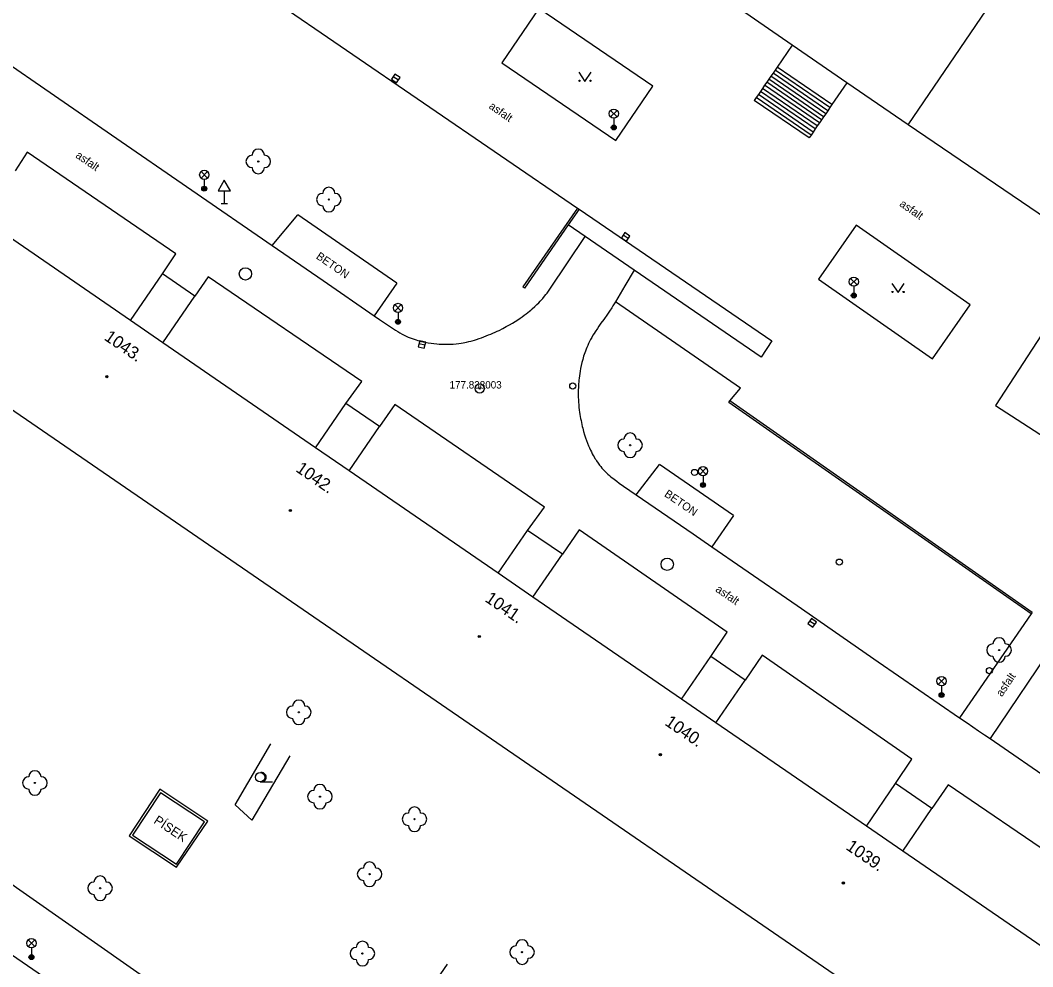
# Model space of a CAD drawing. Extents: x -539515 to -538098, y -1182060 to -1180157.
# Drawn here: x -538629 to -538546.7, y -1181340.3 to -1181263.4 of the extents above; entities that cross this region are included whole.
import ezdxf

# ---------------------------------------------------------------- set-up
doc = ezdxf.new("R2010")
doc.units = 0
for name, color, linetype in [('Vrstva 10', 7, 'Continuous'), ('Vrstva 11', 7, 'Continuous'), ('Vrstva 21', 7, 'Continuous'), ('Vrstva 22', 7, 'Continuous'), ('Vrstva 23', 7, 'Continuous'), ('Vrstva 27', 7, 'Continuous'), ('Vrstva 28', 7, 'Continuous'), ('Vrstva 33', 7, 'Continuous'), ('Vrstva 34', 7, 'Continuous'), ('Vrstva 36', 7, 'Continuous'), ('Vrstva 39', 7, 'Continuous'), ('Vrstva 40', 7, 'Continuous'), ('Vrstva 41', 7, 'Continuous'), ('Vrstva 47', 7, 'Continuous'), ('Vrstva 5', 7, 'Continuous'), ('Vrstva 7', 7, 'Continuous')]:
    doc.layers.add(name, color=color, linetype=linetype)

msp = doc.modelspace()

# ---------------------------------------------------------------- linework, layer by layer
at = {"layer": 'Vrstva 10'}
for p, q in [((-538634.64, -1181263.75), (-538621.575, -1181272.74)), ((-538621.575, -1181272.74), (-538608.51, -1181281.73)), ((-538608.51, -1181281.73), (-538604.369, -1181284.584)), ((-538584.53, -1181283.145), (-538583.1, -1181281.01)), ((-538604.369, -1181284.584), (-538600.23, -1181287.44)), ((-538572.79, -1181306.2), (-538570.276, -1181307.935)), ((-538570.276, -1181307.935), (-538565.881, -1181310.976)), ((-538565.881, -1181310.976), (-538559.29, -1181315.539)), ((-538551.127, -1181321.151), (-538550.658, -1181321.47)), ((-538550.658, -1181321.47), (-538550.19, -1181321.79)), ((-538550.19, -1181321.79), (-538544.771, -1181325.525)), ((-538617.649, -1181325.904), (-538620.15, -1181329.69)), ((-538617.592, -1181326.181), (-538619.873, -1181329.633)), ((-538613.75, -1181328.48), (-538617.649, -1181325.904)), ((-538614.027, -1181328.537), (-538617.592, -1181326.181)), ((-538616.308, -1181331.989), (-538614.027, -1181328.537)), ((-538616.29, -1181332.24), (-538613.75, -1181328.48)), ((-538620.15, -1181329.69), (-538616.29, -1181332.24)), ((-538619.873, -1181329.633), (-538616.308, -1181331.989))]:
    msp.add_line(p, q, dxfattribs=at)
for points in [[(-538590.937, -1181289), (-538590.757, -1181288.925), (-538590.582, -1181288.85), (-538590.413, -1181288.775), (-538590.25, -1181288.699), (-538590.093, -1181288.625), (-538589.789, -1181288.474), (-538589.507, -1181288.326), (-538589.246, -1181288.181), (-538589.004, -1181288.04), (-538588.779, -1181287.903), (-538588.572, -1181287.771), (-538588.38, -1181287.642), (-538588.203, -1181287.519), (-538588.039, -1181287.401), (-538587.888, -1181287.287), (-538587.748, -1181287.178), (-538587.619, -1181287.074), (-538587.5, -1181286.975), (-538587.39, -1181286.88), (-538587.187, -1181286.699), (-538587.015, -1181286.536), (-538586.869, -1181286.39), (-538586.744, -1181286.26), (-538586.637, -1181286.144), (-538586.545, -1181286.041), (-538586.389, -1181285.857), (-538586.277, -1181285.717), (-538586.194, -1181285.609), (-538586.075, -1181285.446), (-538585.96, -1181285.28), (-538584.53, -1181283.145)], [(-538579.12, -1181283.73), (-538579.875, -1181285.02), (-538580.63, -1181286.31), (-538580.735, -1181286.485), (-538580.837, -1181286.648), (-538580.934, -1181286.798), (-538581.121, -1181287.076), (-538581.289, -1181287.317), (-538581.587, -1181287.736), (-538581.811, -1181288.052), (-538581.978, -1181288.291), (-538582.102, -1181288.472), (-538582.284, -1181288.748), (-538582.373, -1181288.888), (-538582.46, -1181289.03), (-538582.559, -1181289.2), (-538582.651, -1181289.368), (-538582.736, -1181289.532), (-538582.814, -1181289.694), (-538582.887, -1181289.852), (-538582.953, -1181290.007), (-538583.015, -1181290.159), (-538583.071, -1181290.307), (-538583.124, -1181290.452), (-538583.172, -1181290.593), (-538583.216, -1181290.731), (-538583.257, -1181290.865), (-538583.294, -1181290.995), (-538583.361, -1181291.25), (-538583.417, -1181291.49), (-538583.465, -1181291.717), (-538583.504, -1181291.93), (-538583.536, -1181292.131), (-538583.563, -1181292.32), (-538583.585, -1181292.497)], [(-538600.23, -1181287.44), (-538599.797, -1181287.737), (-538599.145, -1181288.18), (-538598.49, -1181288.62), (-538598.316, -1181288.732), (-538598.143, -1181288.835), (-538597.971, -1181288.929), (-538597.801, -1181289.016), (-538597.633, -1181289.095), (-538597.468, -1181289.167), (-538597.306, -1181289.233), (-538597.146, -1181289.293), (-538596.99, -1181289.348), (-538596.837, -1181289.398), (-538596.687, -1181289.443), (-538596.54, -1181289.483), (-538596.398, -1181289.52), (-538596.258, -1181289.553), (-538596.123, -1181289.583), (-538595.991, -1181289.609), (-538595.862, -1181289.633), (-538595.612, -1181289.673), (-538595.376, -1181289.703), (-538595.154, -1181289.726), (-538594.945, -1181289.741), (-538594.749, -1181289.751), (-538594.566, -1181289.757), (-538594.394, -1181289.758), (-538594.233, -1181289.756), (-538594.083, -1181289.752), (-538593.942, -1181289.745), (-538593.811, -1181289.737), (-538593.566, -1181289.716), (-538593.353, -1181289.692), (-538593.168, -1181289.666), (-538593.008, -1181289.64), (-538592.869, -1181289.615), (-538592.748, -1181289.59), (-538592.538, -1181289.544), (-538592.383, -1181289.505), (-538592.268, -1181289.474), (-538592.098, -1181289.424), (-538591.93, -1181289.37), (-538591.719, -1181289.298), (-538591.515, -1181289.224), (-538591.316, -1181289.15), (-538591.124, -1181289.076), (-538590.937, -1181289)], [(-538583.585, -1181292.497), (-538583.603, -1181292.663), (-538583.617, -1181292.818), (-538583.629, -1181292.964), (-538583.645, -1181293.237), (-538583.653, -1181293.475), (-538583.656, -1181293.683), (-538583.655, -1181293.863), (-538583.652, -1181294.021), (-538583.641, -1181294.295), (-538583.629, -1181294.499), (-538583.617, -1181294.651), (-538583.596, -1181294.877), (-538583.57, -1181295.1), (-538583.546, -1181295.28), (-538583.52, -1181295.457), (-538583.492, -1181295.629), (-538583.462, -1181295.797), (-538583.431, -1181295.96), (-538583.399, -1181296.119), (-538583.365, -1181296.273), (-538583.331, -1181296.423), (-538583.295, -1181296.568), (-538583.22, -1181296.849), (-538583.143, -1181297.111), (-538583.064, -1181297.356), (-538582.984, -1181297.585), (-538582.904, -1181297.797), (-538582.824, -1181297.994), (-538582.745, -1181298.176), (-538582.667, -1181298.346), (-538582.59, -1181298.503), (-538582.515, -1181298.648), (-538582.442, -1181298.782), (-538582.371, -1181298.907), (-538582.302, -1181299.022), (-538582.236, -1181299.129), (-538582.172, -1181299.227), (-538582.047, -1181299.408), (-538581.933, -1181299.563), (-538581.83, -1181299.695), (-538581.736, -1181299.808), (-538581.652, -1181299.905), (-538581.577, -1181299.988), (-538581.441, -1181300.129), (-538581.335, -1181300.231), (-538581.254, -1181300.306), (-538581.129, -1181300.415), (-538581, -1181300.52), (-538580.745, -1181300.717), (-538580.521, -1181300.885), (-538580.325, -1181301.028)], [(-538580.325, -1181301.028), (-538579.981, -1181301.273)], [(-538579.981, -1181301.273), (-538579.462, -1181301.633), (-538578.94, -1181301.99), (-538575.863, -1181304.093), (-538574.326, -1181305.145), (-538572.79, -1181306.2)], [(-538559.29, -1181315.539), (-538555.992, -1181317.818), (-538554.342, -1181318.955), (-538552.69, -1181320.09), (-538552.066, -1181320.516), (-538551.127, -1181321.151)], [(-538631.15, -1181338.36), (-538630.571, -1181338.752), (-538629.7, -1181339.334), (-538629.264, -1181339.626), (-538628.83, -1181339.92), (-538624.923, -1181342.589)]]:
    msp.add_lwpolyline(points, dxfattribs=at)
at = {"layer": 'Vrstva 11'}
for p, q in [((-538621.123, -1181253.107), (-538583.713, -1181278.704)), ((-538586.85, -1181262.484), (-538589.86, -1181266.91)), ((-538577.59, -1181268.78), (-538586.85, -1181262.484)), ((-538589.86, -1181266.91), (-538580.6, -1181273.206)), ((-538563.384, -1181270.785), (-538567.832, -1181267.733)), ((-538563.214, -1181270.538), (-538567.662, -1181267.486)), ((-538563.044, -1181270.29), (-538567.492, -1181267.238)), ((-538563.893, -1181271.527), (-538568.341, -1181268.475)), ((-538563.723, -1181271.28), (-538568.171, -1181268.228)), ((-538563.554, -1181271.033), (-538568.002, -1181267.981)), ((-538580.6, -1181273.206), (-538577.59, -1181268.78)), ((-538564.402, -1181272.269), (-538568.85, -1181269.217)), ((-538564.233, -1181272.022), (-538568.681, -1181268.97)), ((-538564.063, -1181271.775), (-538568.511, -1181268.723)), ((-538564.89, -1181272.98), (-538569.36, -1181269.96)), ((-538564.742, -1181272.764), (-538569.19, -1181269.712)), ((-538564.572, -1181272.517), (-538569.02, -1181269.465)), ((-538628.43, -1181274.15), (-538629.4, -1181275.68)), ((-538616.34, -1181282.4), (-538628.43, -1181274.15)), ((-538608.51, -1181281.73), (-538606.44, -1181279.25)), ((-538598.404, -1181284.792), (-538606.44, -1181279.25)), ((-538583.59, -1181278.79), (-538567.93, -1181289.48)), ((-538583.1, -1181281.01), (-538584.476, -1181280.067)), ((-538561.09, -1181280.09), (-538564.15, -1181284.46)), ((-538551.82, -1181286.56), (-538561.09, -1181280.09)), ((-538579.12, -1181283.73), (-538583.1, -1181281.01)), ((-538617.43, -1181284.04), (-538616.34, -1181282.4)), ((-538568.8, -1181290.8), (-538579.12, -1181283.73)), ((-538613.73, -1181284.28), (-538614.804, -1181285.844)), ((-538601.25, -1181292.77), (-538613.73, -1181284.28)), ((-538598.404, -1181284.792), (-538600.23, -1181287.44)), ((-538564.15, -1181284.46), (-538554.873, -1181290.935)), ((-538570.48, -1181293.31), (-538580.63, -1181286.31)), ((-538554.873, -1181290.935), (-538551.82, -1181286.56)), ((-538544.914, -1181287.276), (-538549.76, -1181294.73)), ((-538567.93, -1181289.48), (-538568.8, -1181290.8)), ((-538602.53, -1181294.57), (-538601.25, -1181292.77)), ((-538571.34, -1181294.35), (-538570.48, -1181293.31)), ((-538598.56, -1181294.65), (-538599.795, -1181296.448)), ((-538586.4, -1181303), (-538598.56, -1181294.65)), ((-538549.76, -1181294.73), (-538544.386, -1181298.224)), ((-538578.94, -1181301.99), (-538577.06, -1181299.52)), ((-538571.044, -1181303.666), (-538577.06, -1181299.52)), ((-538587.77, -1181304.87), (-538586.4, -1181303)), ((-538571.044, -1181303.666), (-538572.79, -1181306.2)), ((-538583.59, -1181304.83), (-538584.948, -1181306.808)), ((-538571.57, -1181313.13), (-538583.59, -1181304.83)), ((-538540.93, -1181307.99), (-538550.19, -1181321.79)), ((-538546.866, -1181311.663), (-538552.69, -1181320.09)), ((-538572.88, -1181315.11), (-538571.57, -1181313.13)), ((-538568.71, -1181315.02), (-538570.089, -1181317.027)), ((-538556.55, -1181323.45), (-538568.71, -1181315.02)), ((-538557.88, -1181325.44), (-538556.55, -1181323.45)), ((-538553.6, -1181325.54), (-538554.926, -1181327.47)), ((-538541.75, -1181333.61), (-538553.6, -1181325.54)), ((-538632.69, -1181331.5), (-538606.03, -1181350.16))]:
    msp.add_line(p, q, dxfattribs=at)
for points in [[(-538566.272, -1181265.459), (-538571.27, -1181262.03)], [(-538566.272, -1181265.459), (-538567.492, -1181267.238), (-538567.662, -1181267.486), (-538567.832, -1181267.733), (-538568.002, -1181267.981), (-538568.171, -1181268.228), (-538568.341, -1181268.475), (-538568.511, -1181268.723), (-538568.681, -1181268.97), (-538568.85, -1181269.217), (-538569.02, -1181269.465), (-538569.19, -1181269.712), (-538569.36, -1181269.96)], [(-538561.824, -1181268.511), (-538566.272, -1181265.459)], [(-538561.824, -1181268.511), (-538563.044, -1181270.29), (-538563.214, -1181270.538), (-538563.384, -1181270.785), (-538563.554, -1181271.033), (-538563.723, -1181271.28), (-538563.893, -1181271.527), (-538564.063, -1181271.775), (-538564.233, -1181272.022), (-538564.402, -1181272.269), (-538564.572, -1181272.517), (-538564.742, -1181272.764), (-538564.89, -1181272.98)], [(-538556.84, -1181271.93), (-538561.824, -1181268.511)]]:
    msp.add_lwpolyline(points, dxfattribs=at)
at = {"layer": 'Vrstva 21'}
for p, q in [((-538611.54, -1181327.16), (-538608.63, -1181322.21)), ((-538607.09, -1181323.19), (-538610.17, -1181328.4)), ((-538610.17, -1181328.4), (-538611.54, -1181327.16))]:
    msp.add_line(p, q, dxfattribs=at)
for radius in [0.375, 0.05]:
    msp.add_circle((-538591.66, -1181293.35), radius, dxfattribs=at)
at = {"layer": 'Vrstva 22'}
for centre in [(-538609.65, -1181274.91), (-538603.92, -1181278), (-538579.44, -1181297.96), (-538549.46, -1181314.59), (-538606.36, -1181319.65), (-538627.8, -1181325.39), (-538604.64, -1181326.5), (-538596.96, -1181328.33), (-538600.61, -1181332.8), (-538622.5, -1181333.94), (-538601.19, -1181339.24), (-538588.22, -1181339.13)]:
    msp.add_circle(centre, 0.05, dxfattribs=at)
for centre, start, end in [((-538609.65, -1181274.41), 0, 180), ((-538610.15, -1181274.91), 90, 270), ((-538609.15, -1181274.91), 270, 90), ((-538609.65, -1181275.41), 180, 0), ((-538604.42, -1181278), 90, 270), ((-538603.92, -1181277.5), 0, 180), ((-538603.42, -1181278), 270, 90), ((-538603.92, -1181278.5), 180, 0), ((-538579.44, -1181297.46), 0, 180), ((-538579.94, -1181297.96), 90, 270), ((-538578.94, -1181297.96), 270, 90), ((-538579.44, -1181298.46), 180, 0), ((-538549.46, -1181314.09), 0, 180), ((-538549.96, -1181314.59), 90, 270), ((-538548.96, -1181314.59), 270, 90), ((-538549.46, -1181315.09), 180, 0), ((-538606.36, -1181319.15), 0, 180), ((-538606.86, -1181319.65), 90, 270), ((-538605.86, -1181319.65), 270, 90), ((-538606.36, -1181320.15), 180, 0), ((-538627.8, -1181324.89), 0, 180), ((-538628.3, -1181325.39), 90, 270), ((-538627.3, -1181325.39), 270, 90), ((-538627.8, -1181325.89), 180, 0), ((-538605.14, -1181326.5), 90, 270), ((-538604.64, -1181326), 0, 180), ((-538604.14, -1181326.5), 270, 90), ((-538604.64, -1181327), 180, 0), ((-538597.46, -1181328.33), 90, 270), ((-538596.96, -1181327.83), 0, 180), ((-538596.46, -1181328.33), 270, 90), ((-538596.96, -1181328.83), 180, 0), ((-538600.61, -1181332.3), 0, 180), ((-538601.11, -1181332.8), 90, 270), ((-538600.11, -1181332.8), 270, 90), ((-538623, -1181333.94), 90, 270), ((-538622.5, -1181333.44), 0, 180), ((-538622, -1181333.94), 270, 90), ((-538600.61, -1181333.3), 180, 0), ((-538622.5, -1181334.44), 180, 0), ((-538601.19, -1181338.74), 0, 180), ((-538588.22, -1181338.63), 0, 180), ((-538601.69, -1181339.24), 90, 270), ((-538600.69, -1181339.24), 270, 90), ((-538588.72, -1181339.13), 90, 270), ((-538587.72, -1181339.13), 270, 90), ((-538601.19, -1181339.74), 180, 0), ((-538588.22, -1181339.63), 180, 0)]:
    msp.add_arc(centre, 0.5, start, end, dxfattribs=at)
at = {"layer": 'Vrstva 27'}
for p, q in [((-538598.273, -1181268.305), (-538598.685, -1181268.023)), ((-538579.602, -1181281.177), (-538580.014, -1181280.895)), ((-538596.106, -1181289.826), (-538596.594, -1181289.714)), ((-538564.444, -1181312.522), (-538564.856, -1181312.238))]:
    msp.add_line(p, q, dxfattribs=at)
for points in [[(-538598.132, -1181268.099), (-538598.544, -1181267.817), (-538598.826, -1181268.229), (-538598.414, -1181268.511)], [(-538579.461, -1181280.97), (-538579.874, -1181280.689), (-538580.155, -1181281.102), (-538579.742, -1181281.383)], [(-538596.05, -1181289.583), (-538596.537, -1181289.47), (-538596.65, -1181289.957), (-538596.163, -1181290.07)], [(-538564.302, -1181312.317), (-538564.713, -1181312.032), (-538564.998, -1181312.443), (-538564.587, -1181312.728)]]:
    msp.add_lwpolyline(points, close=True, dxfattribs=at)
for centre in [(-538610.7, -1181284.04), (-538576.43, -1181307.63)]:
    msp.add_circle(centre, 0.5, dxfattribs=at)
at = {"layer": 'Vrstva 28'}
for centre in [(-538584.1, -1181293.14), (-538574.21, -1181300.17), (-538562.45, -1181307.45), (-538550.25, -1181316.27)]:
    msp.add_circle(centre, 0.25, dxfattribs=at)
at = {"layer": 'Vrstva 33'}
for p, q in [((-538581.035, -1181271.29), (-538580.505, -1181270.76)), ((-538581.035, -1181270.76), (-538580.505, -1181271.29)), ((-538580.77, -1181271.4), (-538580.77, -1181272.15)), ((-538614.305, -1181276.26), (-538613.775, -1181275.73)), ((-538614.305, -1181275.73), (-538613.775, -1181276.26)), ((-538614.04, -1181276.37), (-538614.04, -1181277.12)), ((-538561.535, -1181284.94), (-538561.005, -1181284.41)), ((-538561.535, -1181284.41), (-538561.005, -1181284.94)), ((-538561.27, -1181285.05), (-538561.27, -1181285.8)), ((-538598.565, -1181287.07), (-538598.035, -1181286.54)), ((-538598.565, -1181286.54), (-538598.035, -1181287.07)), ((-538598.3, -1181287.18), (-538598.3, -1181287.93)), ((-538573.785, -1181300.33), (-538573.255, -1181299.8)), ((-538573.785, -1181299.8), (-538573.255, -1181300.33)), ((-538573.52, -1181300.44), (-538573.52, -1181301.19)), ((-538554.405, -1181317.38), (-538553.875, -1181316.85)), ((-538554.405, -1181316.85), (-538553.875, -1181317.38)), ((-538554.14, -1181317.49), (-538554.14, -1181318.24)), ((-538628.345, -1181338.67), (-538627.815, -1181338.14)), ((-538628.345, -1181338.14), (-538627.815, -1181338.67)), ((-538628.08, -1181338.78), (-538628.08, -1181339.53))]:
    msp.add_line(p, q, dxfattribs=at)
for centre, radius in [((-538580.77, -1181271.025), 0.375), ((-538580.77, -1181272.15), 0.2), ((-538580.77, -1181272.15), 0.145), ((-538580.77, -1181272.15), 0.0876), ((-538614.04, -1181275.995), 0.375), ((-538614.04, -1181277.12), 0.2), ((-538614.04, -1181277.12), 0.145), ((-538614.04, -1181277.12), 0.0876), ((-538561.27, -1181284.675), 0.375), ((-538561.27, -1181285.8), 0.2), ((-538561.27, -1181285.8), 0.145), ((-538561.27, -1181285.8), 0.0876), ((-538598.3, -1181286.805), 0.375), ((-538598.3, -1181287.93), 0.2), ((-538598.3, -1181287.93), 0.145), ((-538598.3, -1181287.93), 0.0876), ((-538573.52, -1181300.065), 0.375), ((-538573.52, -1181301.19), 0.2), ((-538573.52, -1181301.19), 0.145), ((-538573.52, -1181301.19), 0.0876), ((-538554.14, -1181317.115), 0.375), ((-538554.14, -1181318.24), 0.2), ((-538554.14, -1181318.24), 0.145), ((-538554.14, -1181318.24), 0.0876), ((-538628.08, -1181338.405), 0.375), ((-538628.08, -1181339.53), 0.2), ((-538628.08, -1181339.53), 0.145), ((-538628.08, -1181339.53), 0.0876)]:
    msp.add_circle(centre, radius, dxfattribs=at)
at = {"layer": 'Vrstva 34'}
for p, q in [((-538612.414, -1181277.297), (-538612.414, -1181278.315)), ((-538612.664, -1181278.315), (-538612.164, -1181278.315))]:
    msp.add_line(p, q, dxfattribs=at)
msp.add_lwpolyline([(-538612.914, -1181277.297), (-538611.914, -1181277.297), (-538612.414, -1181276.431)], close=True, dxfattribs=at)
at = {"layer": 'Vrstva 36'}
msp.add_line((-538609.504, -1181325.296), (-538608.504, -1181325.296), dxfattribs=at)
for points in [[(-538583.608, -1181267.653), (-538583.108, -1181268.403), (-538582.608, -1181267.653)], [(-538558.174, -1181284.808), (-538557.674, -1181285.558), (-538557.174, -1181284.808)]]:
    msp.add_lwpolyline(points, dxfattribs=at)
for centre, radius in [((-538583.558, -1181268.353), 0.05), ((-538582.659, -1181268.353), 0.05), ((-538558.124, -1181285.508), 0.05), ((-538557.225, -1181285.508), 0.05), ((-538609.504, -1181324.921), 0.375)]:
    msp.add_circle(centre, radius, dxfattribs=at)
msp.add_arc((-538609.379, -1181324.921), 0.375, 260.40593, 99.59406, dxfattribs=at)
at = {"layer": 'Vrstva 39'}
for centre, radius in [((-538621.958, -1181292.384), 0.09), ((-538621.958, -1181292.384), 0.0398), ((-538607.039, -1181303.259), 0.09), ((-538607.039, -1181303.259), 0.0398), ((-538591.693, -1181313.495), 0.09), ((-538591.693, -1181313.495), 0.0398), ((-538576.986, -1181323.091), 0.09), ((-538576.986, -1181323.091), 0.0398), ((-538562.113, -1181333.516), 0.09), ((-538562.113, -1181333.516), 0.0398)]:
    msp.add_circle(centre, radius, dxfattribs=at)
at = {"layer": 'Vrstva 5'}
for p, q in [((-538556.84, -1181271.93), (-538550.09, -1181261.99)), ((-538539.355, -1181283.853), (-538556.84, -1181271.93)), ((-538620.033, -1181287.83), (-538617.43, -1181284.04)), ((-538614.804, -1181285.844), (-538617.43, -1181284.04)), ((-538617.407, -1181289.633), (-538614.804, -1181285.844)), ((-538604.995, -1181298.158), (-538602.53, -1181294.57)), ((-538599.795, -1181296.448), (-538602.53, -1181294.57)), ((-538602.26, -1181300.037), (-538599.795, -1181296.448)), ((-538590.159, -1181308.348), (-538587.77, -1181304.87)), ((-538584.948, -1181306.808), (-538587.77, -1181304.87)), ((-538587.337, -1181310.286), (-538584.948, -1181306.808)), ((-538575.262, -1181318.579), (-538572.88, -1181315.11)), ((-538570.089, -1181317.027), (-538572.88, -1181315.11)), ((-538572.471, -1181320.496), (-538570.089, -1181317.027)), ((-538560.249, -1181328.89), (-538557.88, -1181325.44)), ((-538554.926, -1181327.47), (-538557.88, -1181325.44)), ((-538557.295, -1181330.919), (-538554.926, -1181327.47))]:
    msp.add_line(p, q, dxfattribs=at)
for points in [[(-538620.033, -1181287.83), (-538632.068, -1181279.564)], [(-538647.45, -1181282.86), (-538548.42, -1181350.836)], [(-538617.407, -1181289.633), (-538620.033, -1181287.83)], [(-538604.995, -1181298.158), (-538617.407, -1181289.633)], [(-538602.26, -1181300.037), (-538604.995, -1181298.158)], [(-538590.159, -1181308.348), (-538602.26, -1181300.037)], [(-538587.337, -1181310.286), (-538590.159, -1181308.348)], [(-538575.262, -1181318.579), (-538587.337, -1181310.286)], [(-538572.471, -1181320.496), (-538575.262, -1181318.579)], [(-538560.249, -1181328.89), (-538572.471, -1181320.496)], [(-538557.295, -1181330.919), (-538560.249, -1181328.89)], [(-538545.464, -1181339.044), (-538557.295, -1181330.919)]]:
    msp.add_lwpolyline(points, dxfattribs=at)
at = {"layer": 'Vrstva 7'}
for p, q in [((-538583.713, -1181278.704), (-538588.153, -1181285.104)), ((-538546.78, -1181311.54), (-538571.34, -1181294.35))]:
    msp.add_line(p, q, dxfattribs=at)
for points in [[(-538583.713, -1181278.704), (-538583.59, -1181278.79), (-538584.476, -1181280.067)], [(-538584.476, -1181280.067), (-538588.03, -1181285.19)], [(-538588.03, -1181285.19), (-538588.153, -1181285.104)], [(-538571.426, -1181294.473), (-538571.34, -1181294.35)], [(-538546.866, -1181311.663), (-538571.426, -1181294.473)], [(-538546.78, -1181311.54), (-538546.866, -1181311.663)], [(-538601.38, -1181350.39), (-538594.29, -1181340.11)]]:
    msp.add_lwpolyline(points, dxfattribs=at)

# ---------------------------------------------------------------- texts
at = {"layer": 'Vrstva 22'}
msp.add_text('177.83 ', height=0.6, dxfattribs=at).set_placement((-538594.114, -1181293.35))
at = {"layer": 'Vrstva 23'}
msp.add_text('8003', height=0.6, dxfattribs=at).set_placement((-538591.66, -1181293.35))
at = {"layer": 'Vrstva 40'}
for s, rotation, p in [('asfalt', 325.0864, (-538590.972, -1181270.544)), ('asfalt', 325.46822, (-538624.553, -1181274.543)), ('asfalt', 325.0864, (-538557.611, -1181278.485)), ('BETON', 325.40804, (-538605.01, -1181282.75)), ('BETON', 325.66256, (-538576.717, -1181302.057)), ('asfalt', 325.32994, (-538572.56, -1181309.791)), ('asfalt', 56.13782, (-538549.236, -1181318.437))]:
    msp.add_text(s, height=0.65, rotation=rotation, dxfattribs=at).set_placement(p)
at = {"layer": 'Vrstva 41'}
msp.add_text('PÍSEK', height=0.75, rotation=326.54049, dxfattribs=at).set_placement((-538618.208, -1181328.601))
at = {"layer": 'Vrstva 47'}
for s, p in [('1043.', (-538622.237, -1181289.349)), ('1042.', (-538606.672, -1181300.039)), ('1041.', (-538591.304, -1181310.594)), ('1040.', (-538576.692, -1181320.631)), ('1039.', (-538561.981, -1181330.734))]:
    msp.add_text(s, height=1, rotation=325.51823, dxfattribs=at).set_placement(p)

doc.saveas('drawing.dxf')
